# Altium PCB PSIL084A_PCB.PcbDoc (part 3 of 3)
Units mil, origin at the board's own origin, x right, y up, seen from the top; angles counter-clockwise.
Board outline 8750 x 2700 mil, 4 copper layers (Top Layer, Signal Layer 1, Signal Layer 2, Bottom Layer), stack 61.2 mil thick; 274 components, 214 nets, 1279 pads, 354 vias.
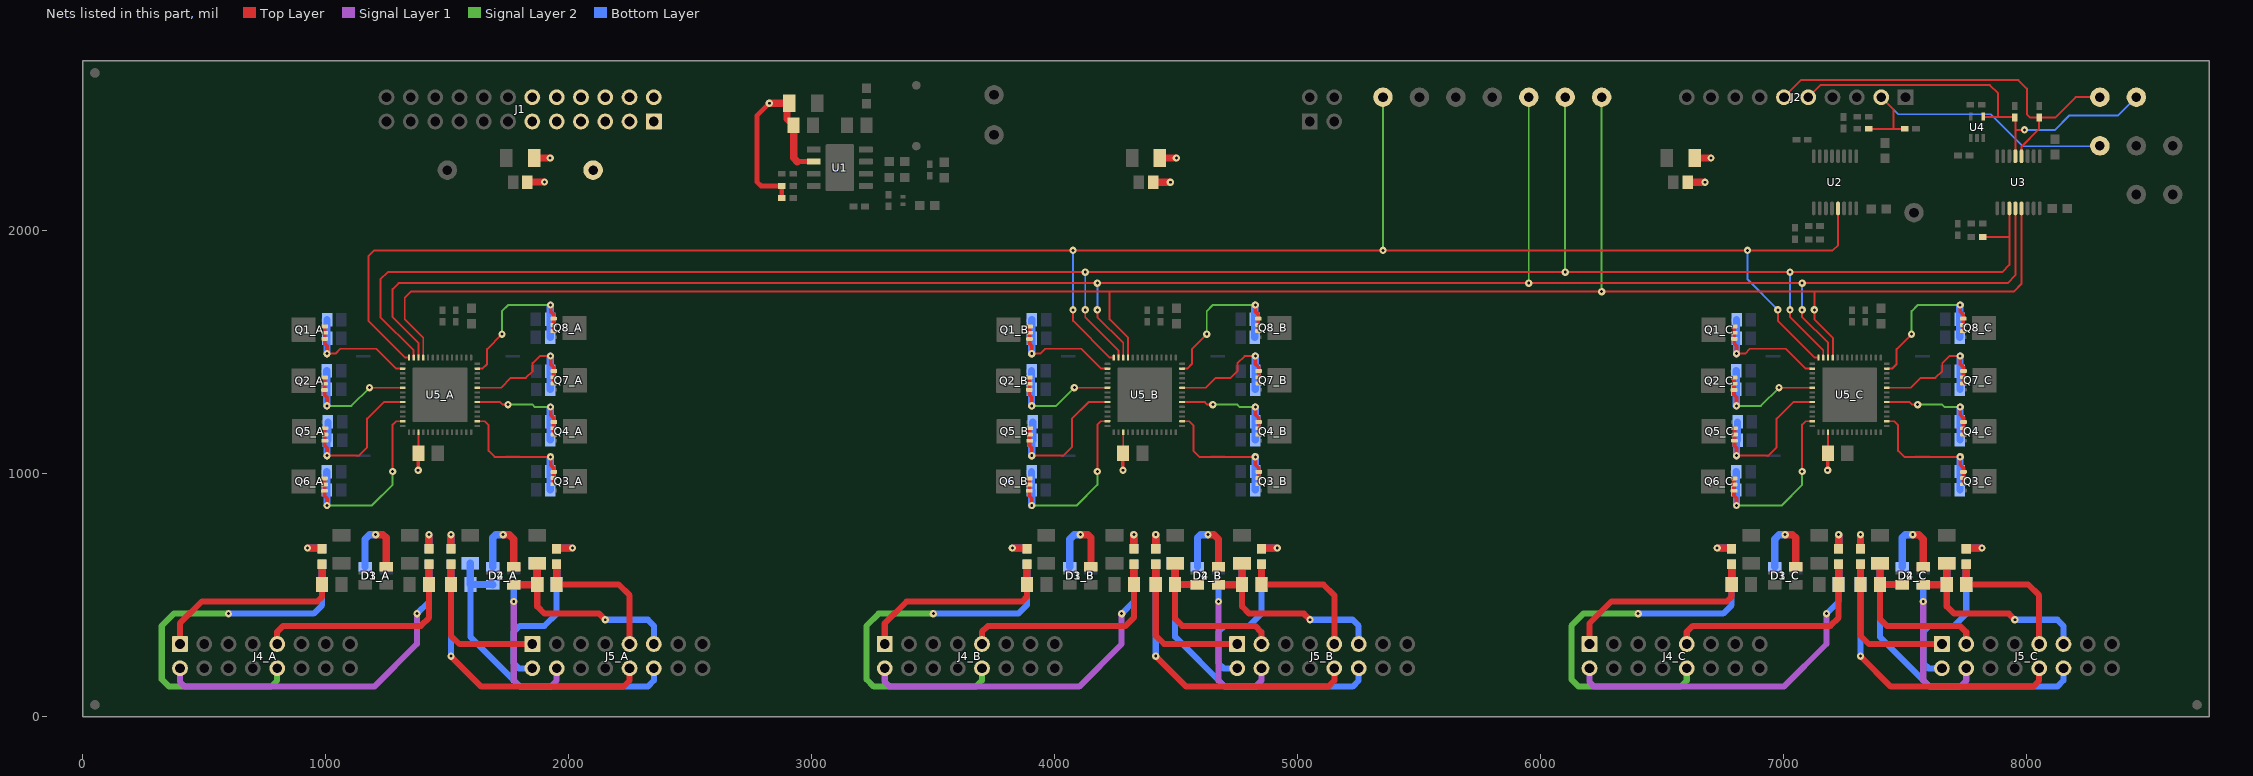
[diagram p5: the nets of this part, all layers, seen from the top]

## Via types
v1: diameter 30, hole 12, Top Layer to Bottom Layer, 282 vias
v2: diameter 19.68, hole 7.87, Top Layer to Bottom Layer, 67 vias
v3: diameter 19.68, hole 7.87, Top Layer to Bottom Layer, tented both sides, 4 vias
v4: diameter 34, hole 16, Top Layer to Bottom Layer, 1 vias

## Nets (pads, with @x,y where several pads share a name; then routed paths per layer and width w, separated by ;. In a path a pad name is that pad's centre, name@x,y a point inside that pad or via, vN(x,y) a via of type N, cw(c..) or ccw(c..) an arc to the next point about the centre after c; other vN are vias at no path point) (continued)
PSE_N5_B: C22_B.2 D2_B.2 F3_B.1 J5_B.3 | length 748.5
  Top Layer w25: C22_B.2@4495,545 4495,403.31 4523.31,375 4824.13,375 4850,349.13 J5_B.3@4850,300
  Top Layer w30: F3_B.1@4495,632.91 C22_B.2@4495,545 4585.2,545 D2_B.2@4586.69,543.5
PSE_N5_C: C22_C.2 D2_C.2 F3_C.1 J5_C.3 | length 748.5
  Top Layer w25: C22_C.2@7395,545 7395,403.31 7423.31,375 7724.13,375 7750,349.13 J5_C.3@7750,300
  Top Layer w30: F3_C.1@7395,632.91 C22_C.2@7395,545 7485.2,545 D2_C.2@7486.69,543.5
PSE_N6_A: C23_A.2 D2_A.3 F4_A.1 J5_A.11 | length 863.4
  Top Layer w25: C23_A.2@1870,545 1870,455 1900,425 2125,425 v1(2150,400)
  Top Layer w30: D2_A.3@1773.31,543.5 1868.5,543.5 C23_A.2@1870,545 F4_A.1@1870,632.91
  Bottom Layer w25: v1(2150,400) 2325,400 2350,375 J5_A.11@2350,300
PSE_N6_B: C23_B.2 D2_B.3 F4_B.1 J5_B.11 | length 863.4
  Top Layer w25: C23_B.2@4770,545 4770,455 4800,425 5025,425 v1(5050,400)
  Top Layer w30: D2_B.3@4673.31,543.5 4768.5,543.5 C23_B.2@4770,545 F4_B.1@4770,632.91
  Bottom Layer w25: v1(5050,400) 5225,400 5250,375 J5_B.11@5250,300
PSE_N6_C: C23_C.2 D2_C.3 F4_C.1 J5_C.11 | length 863.4
  Top Layer w25: C23_C.2@7670,545 7670,455 7700,425 7925,425 v1(7950,400)
  Top Layer w30: D2_C.3@7573.31,543.5 7668.5,543.5 C23_C.2@7670,545 F4_C.1@7670,632.91
  Bottom Layer w25: v1(7950,400) 8125,400 8150,375 J5_C.11@8150,300
PSE_N7_A: C26_A.2 D4_A.2 F7_A.1 J5_A.4 | length 826.1
  Signal Layer 1 w25: v1(1773.31,474.98) 1773.31,150 1798.31,125 1925,125 1950,150 J5_A.4@1950,200
  Bottom Layer w25: v1(1773.31,474.98) D4_A.2@1773.31,543.5
  Bottom Layer w30: D4_A.2@1773.31,543.5 1774.8,545 C26_A.2@1870,545 F7_A.1@1870,632.91
PSE_N7_B: C26_B.2 D4_B.2 F7_B.1 J5_B.4 | length 826.1
  Signal Layer 1 w25: v1(4673.31,474.98) 4673.31,150 4698.31,125 4825,125 4850,150 J5_B.4@4850,200
  Bottom Layer w25: v1(4673.31,474.98) D4_B.2@4673.31,543.5
  Bottom Layer w30: D4_B.2@4673.31,543.5 4674.8,545 C26_B.2@4770,545 F7_B.1@4770,632.91
PSE_N7_C: C26_C.2 D4_C.2 F7_C.1 J5_C.4 | length 826.1
  Signal Layer 1 w25: v1(7573.31,474.98) 7573.31,150 7598.31,125 7725,125 7750,150 J5_C.4@7750,200
  Bottom Layer w25: v1(7573.31,474.98) D4_C.2@7573.31,543.5
  Bottom Layer w30: D4_C.2@7573.31,543.5 7574.8,545 C26_C.2@7670,545 F7_C.1@7670,632.91
PSE_N8_A: C27_A.2 D4_A.3 F8_A.1 J5_A.12 | length 1295.5
  Bottom Layer w25: C27_A.2@1595,545 1595,330 1800,125 2325,125 2350,150 J5_A.12@2350,200
  Bottom Layer w30: F8_A.1@1595,632.91 C27_A.2@1595,545 1685.2,545 D4_A.3@1686.69,543.5
PSE_N8_B: C27_B.2 D4_B.3 F8_B.1 J5_B.12 | length 1295.5
  Bottom Layer w25: C27_B.2@4495,545 4495,330 4700,125 5225,125 5250,150 J5_B.12@5250,200
  Bottom Layer w30: F8_B.1@4495,632.91 C27_B.2@4495,545 4585.2,545 D4_B.3@4586.69,543.5
PSE_N8_C: C27_C.2 D4_C.3 F8_C.1 J5_C.12 | length 1295.5
  Bottom Layer w25: C27_C.2@7395,545 7395,330 7600,125 8125,125 8150,150 J5_C.12@8150,200
  Bottom Layer w30: F8_C.1@7395,632.91 C27_C.2@7395,545 7485.2,545 D4_C.3@7486.69,543.5
PSE_OSS: TP12.1 U2.13 U5_A.56 U5_B.56 U5_C.56 | length 8434
  Top Layer w8: U5_A.56@1342.05,1478.54 1326.46,1478.54 1175,1630 1175,1895 1200,1920 v1(4075,1920) v1(5350,1920) v1(6850,1920) 7200.79,1920 7222.5,1941.71 U2.13@7222.5,2092.72 ; v1(4075,1675) 4075,1630 4226.46,1478.54 U5_B.56@4242.05,1478.54 ; v1(6975,1675) 6975,1630 7126.46,1478.54 U5_C.56@7142.05,1478.54
  Signal Layer 2 w8: v1(5350,1920) TP12.1@5350,2550
  Bottom Layer w8: v1(4075,1675) v1(4075,1920) ; v1(6850,1920) 6850,1800 v1(6975,1675)
PSE_P1_A: C20_A.1 J4_A.1 L2_A.2 | length 849.1
  Top Layer w25: J4_A.1@400,300 400,385 490,475 965,475 985,495 C20_A.1@985,545
  Top Layer w30: C20_A.1@985,545 L2_A.2@985,628.5
PSE_P1_B: C20_B.1 J4_B.1 L2_B.2 | length 849.1
  Top Layer w25: J4_B.1@3300,300 3300,385 3390,475 3865,475 3885,495 C20_B.1@3885,545
  Top Layer w30: C20_B.1@3885,545 L2_B.2@3885,628.5
PSE_P1_C: C20_C.1 J4_C.1 L2_C.2 | length 849.1
  Top Layer w25: J4_C.1@6200,300 6200,385 6290,475 6765,475 6785,495 C20_C.1@6785,545
  Top Layer w30: C20_C.1@6785,545 L2_C.2@6785,628.5
PSE_P2_A: C21_A.1 J4_A.9 L3_A.2 | length 919.1
  Top Layer w25: J4_A.9@800,300 800,350 825,375 1391.3,375 1425,408.7 C21_A.1@1425,545
  Top Layer w30: C21_A.1@1425,545 L3_A.2@1425,628.5
PSE_P2_B: C21_B.1 J4_B.9 L3_B.2 | length 919.1
  Top Layer w25: J4_B.9@3700,300 3700,350 3725,375 4291.3,375 4325,408.7 C21_B.1@4325,545
  Top Layer w30: C21_B.1@4325,545 L3_B.2@4325,628.5
PSE_P2_C: C21_C.1 J4_C.9 L3_C.2 | length 919.1
  Top Layer w25: J4_C.9@6600,300 6600,350 6625,375 7191.3,375 7225,408.7 C21_C.1@7225,545
  Top Layer w30: C21_C.1@7225,545 L3_C.2@7225,628.5
PSE_P3_A: C24_A.1 J4_A.2 L6_A.2 | length 1460
  Signal Layer 1 w25: J4_A.2@400,200 400,145 420,125 1200,125 1375.02,300.02 v1(1375.02,425)
  Bottom Layer w25: v1(1375.02,425) 1425,474.98 C24_A.1@1425,545
  Bottom Layer w30: C24_A.1@1425,545 L6_A.2@1425,628.5
PSE_P3_B: C24_B.1 J4_B.2 L6_B.2 | length 1460
  Signal Layer 1 w25: J4_B.2@3300,200 3300,145 3320,125 4100,125 4275.02,300.02 v1(4275.02,425)
  Bottom Layer w25: v1(4275.02,425) 4325,474.98 C24_B.1@4325,545
  Bottom Layer w30: C24_B.1@4325,545 L6_B.2@4325,628.5
PSE_P3_C: C24_C.1 J4_C.2 L6_C.2 | length 1460
  Signal Layer 1 w25: J4_C.2@6200,200 6200,145 6220,125 7000,125 7175.02,300.02 v1(7175.02,425)
  Bottom Layer w25: v1(7175.02,425) 7225,474.98 C24_C.1@7225,545
  Bottom Layer w30: C24_C.1@7225,545 L6_C.2@7225,628.5
PSE_P4_A: C25_A.1 J4_A.10 L7_A.2 | length 1631.5
  Signal Layer 2 w25: v1(600,425) 375,425 325,375 325,155 355,125 775,125 800,150 J4_A.10@800,200
  Bottom Layer w25: v1(600,425) 950,425 985,460 C25_A.1@985,545
  Bottom Layer w30: C25_A.1@985,545 L7_A.2@985,628.5
PSE_P4_B: C25_B.1 J4_B.10 L7_B.2 | length 1631.5
  Signal Layer 2 w25: v1(3500,425) 3275,425 3225,375 3225,155 3255,125 3675,125 3700,150 J4_B.10@3700,200
  Bottom Layer w25: v1(3500,425) 3850,425 3885,460 C25_B.1@3885,545
  Bottom Layer w30: C25_B.1@3885,545 L7_B.2@3885,628.5
PSE_P4_C: C25_C.1 J4_C.10 L7_C.2 | length 1631.5
  Signal Layer 2 w25: v1(6400,425) 6175,425 6125,375 6125,155 6155,125 6575,125 6600,150 J4_C.10@6600,200
  Bottom Layer w25: v1(6400,425) 6750,425 6785,460 C25_C.1@6785,545
  Bottom Layer w30: C25_C.1@6785,545 L7_C.2@6785,628.5
PSE_P5_A: C22_A.1 J5_A.1 L4_A.2 | length 643.2
  Top Layer w25: C22_A.1@1515,545 1515,334.74 1549.74,300 J5_A.1@1850,300
  Top Layer w30: C22_A.1@1515,545 L4_A.2@1515,628.5
PSE_P5_B: C22_B.1 J5_B.1 L4_B.2 | length 643.2
  Top Layer w25: C22_B.1@4415,545 4415,334.74 4449.74,300 J5_B.1@4750,300
  Top Layer w30: C22_B.1@4415,545 L4_B.2@4415,628.5
PSE_P5_C: C22_C.1 J5_C.1 L4_C.2 | length 643.2
  Top Layer w25: C22_C.1@7315,545 7315,334.74 7349.74,300 J5_C.1@7650,300
  Top Layer w30: C22_C.1@7315,545 L4_C.2@7315,628.5
PSE_P6_A: C23_A.1 J5_A.9 L5_A.2 | length 602.1
  Top Layer w25: C23_A.1@1950,545 2205,545 2250,500 J5_A.9@2250,300
  Top Layer w30: C23_A.1@1950,545 L5_A.2@1950,628.5
PSE_P6_B: C23_B.1 J5_B.9 L5_B.2 | length 602.1
  Top Layer w25: C23_B.1@4850,545 5105,545 5150,500 J5_B.9@5150,300
  Top Layer w30: C23_B.1@4850,545 L5_B.2@4850,628.5
PSE_P6_C: C23_C.1 J5_C.9 L5_C.2 | length 602.1
  Top Layer w25: C23_C.1@7750,545 8005,545 8050,500 J5_C.9@8050,300
  Top Layer w30: C23_C.1@7750,545 L5_C.2@7750,628.5
PSE_P7_A: C26_A.1 J5_A.2 L8_A.2 | length 625.2
  Bottom Layer w25: J5_A.2@1850,200 1795,200 1773.31,221.69 1773.31,350 1798.31,375 1900,375 1950,425 C26_A.1@1950,545
  Bottom Layer w30: C26_A.1@1950,545 L8_A.2@1950,628.5
PSE_P7_B: C26_B.1 J5_B.2 L8_B.2 | length 625.2
  Bottom Layer w25: J5_B.2@4750,200 4695,200 4673.31,221.69 4673.31,350 4698.31,375 4800,375 4850,425 C26_B.1@4850,545
  Bottom Layer w30: C26_B.1@4850,545 L8_B.2@4850,628.5
PSE_P7_C: C26_C.1 J5_C.2 L8_C.2 | length 625.2
  Bottom Layer w25: J5_C.2@7650,200 7595,200 7573.31,221.69 7573.31,350 7598.31,375 7700,375 7750,425 C26_C.1@7750,545
  Bottom Layer w30: C26_C.1@7750,545 L8_C.2@7750,628.5
PSE_P8_A: C27_A.1 J5_A.10 L9_A.2 | length 1225.6
  Top Layer w25: v1(1515,250) 1640,125 2225,125 2250,150 J5_A.10@2250,200
  Bottom Layer w25: v1(1515,250) C27_A.1@1515,545
  Bottom Layer w30: C27_A.1@1515,545 L9_A.2@1515,628.5
PSE_P8_B: C27_B.1 J5_B.10 L9_B.2 | length 1225.6
  Top Layer w25: v1(4415,250) 4540,125 5125,125 5150,150 J5_B.10@5150,200
  Bottom Layer w25: v1(4415,250) C27_B.1@4415,545
  Bottom Layer w30: C27_B.1@4415,545 L9_B.2@4415,628.5
PSE_P8_C: C27_C.1 J5_C.10 L9_C.2 | length 1225.6
  Top Layer w25: v1(7315,250) 7440,125 8025,125 8050,150 J5_C.10@8050,200
  Bottom Layer w25: v1(7315,250) C27_C.1@7315,545
  Bottom Layer w30: C27_C.1@7315,545 L9_C.2@7315,628.5
PSE_S1_A: Q1_A.1 Q1_A.2 Q1_A.3 R21_A.1 R22_A.1 U5_A.2 | length 608.1
  Top Layer w8: v1(1005,1495) 1040,1495 1060,1515 1208.27,1515 1290,1433.27 U5_A.2@1316.46,1433.27
  Top Layer w15: Q1_A.3@995.69,1606.71 Q1_A.2@995.69,1581.12 Q1_A.1@995.69,1555.53 995.69,1536.73 1005,1527.42 v1(1005,1495)
  Bottom Layer w30: v1(1005,1495) 1005.14,1495.14 R22_A.1@1005.14,1558.92 R21_A.1@1005.14,1633.92
PSE_S1_B: Q1_B.1 Q1_B.2 Q1_B.3 R21_B.1 R22_B.1 U5_B.2 | length 608.1
  Top Layer w8: v1(3905,1495) 3940,1495 3960,1515 4108.27,1515 4190,1433.27 U5_B.2@4216.46,1433.27
  Top Layer w15: Q1_B.3@3895.69,1606.71 Q1_B.2@3895.69,1581.12 Q1_B.1@3895.69,1555.53 3895.69,1536.73 3905,1527.42 v1(3905,1495)
  Bottom Layer w30: v1(3905,1495) 3905.14,1495.14 R22_B.1@3905.14,1558.92 R21_B.1@3905.14,1633.92
PSE_S1_C: Q1_C.1 Q1_C.2 Q1_C.3 R21_C.1 R22_C.1 U5_C.2 | length 608.1
  Top Layer w8: v1(6805,1495) 6840,1495 6860,1515 7008.27,1515 7090,1433.27 U5_C.2@7116.46,1433.27
  Top Layer w15: Q1_C.3@6795.69,1606.71 Q1_C.2@6795.69,1581.12 Q1_C.1@6795.69,1555.53 6795.69,1536.73 6805,1527.42 v1(6805,1495)
  Bottom Layer w30: v1(6805,1495) 6805.14,1495.14 R22_C.1@6805.14,1558.92 R21_C.1@6805.14,1633.92
PSE_S2_A: Q2_A.1 Q2_A.2 Q2_A.3 R23_A.1 R24_A.1 U5_A.6 | length 608.1
  Top Layer w8: v1(1180,1355) 1180.47,1354.53 U5_A.6@1316.46,1354.53
  Top Layer w15: Q2_A.3@994.59,1396.71 Q2_A.2@994.59,1371.12 Q2_A.1@994.59,1345.53 994.59,1325.55 1005,1315.14 v1(1005,1280)
  Signal Layer 2 w8: v1(1005,1280) 1105,1280 v1(1180,1355)
  Bottom Layer w30: R23_A.1@1004.04,1423.92 R24_A.1@1004.04,1348.92 1004.04,1280.96 v1(1005,1280)
PSE_S2_B: Q2_B.1 Q2_B.2 Q2_B.3 R23_B.1 R24_B.1 U5_B.6 | length 608.1
  Top Layer w8: v1(4080,1355) 4080.47,1354.53 U5_B.6@4216.46,1354.53
  Top Layer w15: Q2_B.3@3894.59,1396.71 Q2_B.2@3894.59,1371.12 Q2_B.1@3894.59,1345.53 3894.59,1325.55 3905,1315.14 v1(3905,1280)
  Signal Layer 2 w8: v1(3905,1280) 4005,1280 v1(4080,1355)
  Bottom Layer w30: R23_B.1@3904.04,1423.92 R24_B.1@3904.04,1348.92 3904.04,1280.96 v1(3905,1280)
PSE_S2_C: Q2_C.1 Q2_C.2 Q2_C.3 R23_C.1 R24_C.1 U5_C.6 | length 608.1
  Top Layer w8: v1(6980,1355) 6980.47,1354.53 U5_C.6@7116.46,1354.53
  Top Layer w15: Q2_C.3@6794.59,1396.71 Q2_C.2@6794.59,1371.12 Q2_C.1@6794.59,1345.53 6794.59,1325.55 6805,1315.14 v1(6805,1280)
  Signal Layer 2 w8: v1(6805,1280) 6905,1280 v1(6980,1355)
  Bottom Layer w30: R23_C.1@6804.04,1423.92 R24_C.1@6804.04,1348.92 6804.04,1280.96 v1(6805,1280)
PSE_S3_A: Q5_A.1 Q5_A.2 Q5_A.3 R29_A.1 R30_A.1 U5_A.9 | length 728.3
  Top Layer w8: v1(1005,1075) 1135,1075 1170,1110 1170,1227.07 1238.4,1295.47 U5_A.9@1316.46,1295.47
  Top Layer w15: Q5_A.3@996.42,1187.8 Q5_A.2@996.42,1162.2 Q5_A.1@996.42,1136.61 996.42,1116 1005,1107.42 v1(1005,1075)
  Bottom Layer w30: v1(1005,1075) 1005,1134.88 R30_A.1@1009.04,1138.92 R29_A.1@1009.04,1213.92
PSE_S3_B: Q5_B.1 Q5_B.2 Q5_B.3 R29_B.1 R30_B.1 U5_B.9 | length 728.3
  Top Layer w8: v1(3905,1075) 4035,1075 4070,1110 4070,1227.07 4138.4,1295.47 U5_B.9@4216.46,1295.47
  Top Layer w15: Q5_B.3@3896.42,1187.8 Q5_B.2@3896.42,1162.2 Q5_B.1@3896.42,1136.61 3896.42,1116 3905,1107.42 v1(3905,1075)
  Bottom Layer w30: v1(3905,1075) 3905,1134.88 R30_B.1@3909.04,1138.92 R29_B.1@3909.04,1213.92
PSE_S3_C: Q5_C.1 Q5_C.2 Q5_C.3 R29_C.1 R30_C.1 U5_C.9 | length 728.3
  Top Layer w8: v1(6805,1075) 6935,1075 6970,1110 6970,1227.07 7038.4,1295.47 U5_C.9@7116.46,1295.47
  Top Layer w15: Q5_C.3@6796.42,1187.8 Q5_C.2@6796.42,1162.2 Q5_C.1@6796.42,1136.61 6796.42,1116 6805,1107.42 v1(6805,1075)
  Bottom Layer w30: v1(6805,1075) 6805,1134.88 R30_C.1@6809.04,1138.92 R29_C.1@6809.04,1213.92
PSE_S4_A: Q6_A.1 Q6_A.2 Q6_A.3 R31_A.1 R32_A.1 U5_A.13 | length 855.5
  Top Layer w8: v1(1275,1010) 1275,1202.66 1289.07,1216.73 U5_A.13@1316.46,1216.73
  Top Layer w15: Q6_A.3@994.59,981.71 Q6_A.2@994.59,956.12 Q6_A.1@994.59,930.53 994.59,910.41 1005,900 v1(1005,870)
  Signal Layer 2 w8: v1(1005,870) 1190,870 1275,955 v1(1275,1010)
  Bottom Layer w30: R31_A.1@1004.04,1008.92 R32_A.1@1004.04,933.92 1005,932.95 v1(1005,870)
PSE_S4_B: Q6_B.1 Q6_B.2 Q6_B.3 R31_B.1 R32_B.1 U5_B.13 | length 855.5
  Top Layer w8: v1(4175,1010) 4175,1202.66 4189.07,1216.73 U5_B.13@4216.46,1216.73
  Top Layer w15: Q6_B.3@3894.59,981.71 Q6_B.2@3894.59,956.12 Q6_B.1@3894.59,930.53 3894.59,910.41 3905,900 v1(3905,870)
  Signal Layer 2 w8: v1(3905,870) 4090,870 4175,955 v1(4175,1010)
  Bottom Layer w30: R31_B.1@3904.04,1008.92 R32_B.1@3904.04,933.92 3905,932.95 v1(3905,870)
PSE_S4_C: Q6_C.1 Q6_C.2 Q6_C.3 R31_C.1 R32_C.1 U5_C.13 | length 855.5
  Top Layer w8: v1(7075,1010) 7075,1202.66 7089.07,1216.73 U5_C.13@7116.46,1216.73
  Top Layer w15: Q6_C.3@6794.59,981.71 Q6_C.2@6794.59,956.12 Q6_C.1@6794.59,930.53 6794.59,910.41 6805,900 v1(6805,870)
  Signal Layer 2 w8: v1(6805,870) 6990,870 7075,955 v1(7075,1010)
  Bottom Layer w30: R31_C.1@6804.04,1008.92 R32_C.1@6804.04,933.92 6805,932.95 v1(6805,870)
PSE_S5_A: Q3_A.1 Q3_A.2 Q3_A.3 R25_A.1 R26_A.1 U5_A.30 | length 677.5
  Top Layer w8: U5_A.30@1623.54,1216.73 1653.27,1216.73 1670,1200 1670,1095 1695,1070 v1(1925,1070)
  Top Layer w15: v1(1925,1070) 1925,1037.46 1938.58,1023.88 Q3_A.1@1938.58,1008.39 Q3_A.2@1938.58,982.8 Q3_A.3@1938.58,957.2
  Bottom Layer w30: R26_A.1@1924.13,935 R25_A.1@1924.13,1010 1924.13,1069.13 v1(1925,1070)
PSE_S5_B: Q3_B.1 Q3_B.2 Q3_B.3 R25_B.1 R26_B.1 U5_B.30 | length 677.5
  Top Layer w8: U5_B.30@4523.54,1216.73 4553.27,1216.73 4570,1200 4570,1095 4595,1070 v1(4825,1070)
  Top Layer w15: v1(4825,1070) 4825,1037.46 4838.58,1023.88 Q3_B.1@4838.58,1008.39 Q3_B.2@4838.58,982.8 Q3_B.3@4838.58,957.2
  Bottom Layer w30: R26_B.1@4824.13,935 R25_B.1@4824.13,1010 4824.13,1069.13 v1(4825,1070)
PSE_S5_C: Q3_C.1 Q3_C.2 Q3_C.3 R25_C.1 R26_C.1 U5_C.30 | length 677.5
  Top Layer w8: U5_C.30@7423.54,1216.73 7453.27,1216.73 7470,1200 7470,1095 7495,1070 v1(7725,1070)
  Top Layer w15: v1(7725,1070) 7725,1037.46 7738.58,1023.88 Q3_C.1@7738.58,1008.39 Q3_C.2@7738.58,982.8 Q3_C.3@7738.58,957.2
  Bottom Layer w30: R26_C.1@7724.13,935 R25_C.1@7724.13,1010 7724.13,1069.13 v1(7725,1070)
PSE_S6_A: Q4_A.1 Q4_A.2 Q4_A.3 R27_A.1 R28_A.1 U5_A.34 | length 563.7
  Top Layer w8: U5_A.34@1623.54,1295.47 1716.91,1295.47 1727.39,1285 v1(1750,1285)
  Top Layer w15: v1(1925,1275) 1925,1243.54 1938.58,1229.96 Q4_A.1@1938.58,1213.39 Q4_A.2@1938.58,1187.8 Q4_A.3@1938.58,1162.2
  Signal Layer 2 w8: v1(1750,1285) 1850.79,1285 1860.79,1275 v1(1925,1275)
  Bottom Layer w30: R28_A.1@1924.13,1140 R27_A.1@1924.13,1215 1924.13,1274.13 v1(1925,1275)
PSE_S6_B: Q4_B.1 Q4_B.2 Q4_B.3 R27_B.1 R28_B.1 U5_B.34 | length 563.7
  Top Layer w8: U5_B.34@4523.54,1295.47 4616.91,1295.47 4627.39,1285 v1(4650,1285)
  Top Layer w15: v1(4825,1275) 4825,1243.54 4838.58,1229.96 Q4_B.1@4838.58,1213.39 Q4_B.2@4838.58,1187.8 Q4_B.3@4838.58,1162.2
  Signal Layer 2 w8: v1(4650,1285) 4750.79,1285 4760.79,1275 v1(4825,1275)
  Bottom Layer w30: R28_B.1@4824.13,1140 R27_B.1@4824.13,1215 4824.13,1274.13 v1(4825,1275)
PSE_S6_C: Q4_C.1 Q4_C.2 Q4_C.3 R27_C.1 R28_C.1 U5_C.34 | length 563.7
  Top Layer w8: U5_C.34@7423.54,1295.47 7516.91,1295.47 7527.39,1285 v1(7550,1285)
  Top Layer w15: v1(7725,1275) 7725,1243.54 7738.58,1229.96 Q4_C.1@7738.58,1213.39 Q4_C.2@7738.58,1187.8 Q4_C.3@7738.58,1162.2
  Signal Layer 2 w8: v1(7550,1285) 7650.79,1285 7660.79,1275 v1(7725,1275)
  Bottom Layer w30: R28_C.1@7724.13,1140 R27_C.1@7724.13,1215 7724.13,1274.13 v1(7725,1275)
PSE_S7_A: Q7_A.1 Q7_A.2 Q7_A.3 R33_A.1 R34_A.1 U5_A.37 | length 631
  Top Layer w8: U5_A.37@1623.54,1354.53 1721.5,1354.53 1761.97,1395 1823.5,1395 1851.3,1422.8 1851.3,1455.43 1880.87,1485 v1(1925,1485)
  Top Layer w15: v1(1925,1485) 1925,1452.39 1938.58,1438.81 Q7_A.1@1938.58,1423.39 Q7_A.2@1938.58,1397.8 Q7_A.3@1938.58,1372.2
  Bottom Layer w30: R34_A.1@1924.13,1347.39 R33_A.1@1924.13,1422.39 1924.13,1484.13 v1(1925,1485)
PSE_S7_B: Q7_B.1 Q7_B.2 Q7_B.3 R33_B.1 R34_B.1 U5_B.37 | length 631
  Top Layer w8: U5_B.37@4523.54,1354.53 4621.5,1354.53 4661.97,1395 4723.5,1395 4751.3,1422.8 4751.3,1455.43 4780.87,1485 v1(4825,1485)
  Top Layer w15: v1(4825,1485) 4825,1452.39 4838.58,1438.81 Q7_B.1@4838.58,1423.39 Q7_B.2@4838.58,1397.8 Q7_B.3@4838.58,1372.2
  Bottom Layer w30: R34_B.1@4824.13,1347.39 R33_B.1@4824.13,1422.39 4824.13,1484.13 v1(4825,1485)
PSE_S7_C: Q7_C.1 Q7_C.2 Q7_C.3 R33_C.1 R34_C.1 U5_C.37 | length 631
  Top Layer w8: U5_C.37@7423.54,1354.53 7521.5,1354.53 7561.97,1395 7623.5,1395 7651.3,1422.8 7651.3,1455.43 7680.87,1485 v1(7725,1485)
  Top Layer w15: v1(7725,1485) 7725,1452.39 7738.58,1438.81 Q7_C.1@7738.58,1423.39 Q7_C.2@7738.58,1397.8 Q7_C.3@7738.58,1372.2
  Bottom Layer w30: R34_C.1@7724.13,1347.39 R33_C.1@7724.13,1422.39 7724.13,1484.13 v1(7725,1485)
PSE_S8_A: Q8_A.1 Q8_A.2 Q8_A.3 R35_A.1 R36_A.1 U5_A.41 | length 748.3
  Top Layer w8: U5_A.41@1623.54,1433.27 1644.62,1433.27 1663.58,1452.23 1663.58,1513.58 v1(1725,1575)
  Top Layer w15: v1(1925,1695) 1925,1667.99 1937.48,1655.51 Q8_A.1@1937.48,1638.87 Q8_A.2@1937.48,1613.28 Q8_A.3@1937.48,1587.69
  Signal Layer 2 w8: v1(1725,1575) 1725,1670 1750,1695 v1(1925,1695)
  Bottom Layer w30: R36_A.1@1923.03,1561.5 R35_A.1@1923.03,1636.5 1923.03,1693.03 v1(1925,1695)
PSE_S8_B: Q8_B.1 Q8_B.2 Q8_B.3 R35_B.1 R36_B.1 U5_B.41 | length 748.3
  Top Layer w8: U5_B.41@4523.54,1433.27 4544.62,1433.27 4563.58,1452.23 4563.58,1513.58 v1(4625,1575)
  Top Layer w15: v1(4825,1695) 4825,1667.99 4837.48,1655.51 Q8_B.1@4837.48,1638.87 Q8_B.2@4837.48,1613.28 Q8_B.3@4837.48,1587.69
  Signal Layer 2 w8: v1(4625,1575) 4625,1670 4650,1695 v1(4825,1695)
  Bottom Layer w30: R36_B.1@4823.03,1561.5 R35_B.1@4823.03,1636.5 4823.03,1693.03 v1(4825,1695)
PSE_S8_C: Q8_C.1 Q8_C.2 Q8_C.3 R35_C.1 R36_C.1 U5_C.41 | length 748.3
  Top Layer w8: U5_C.41@7423.54,1433.27 7444.62,1433.27 7463.58,1452.23 7463.58,1513.58 v1(7525,1575)
  Top Layer w15: v1(7725,1695) 7725,1667.99 7737.48,1655.51 Q8_C.1@7737.48,1638.87 Q8_C.2@7737.48,1613.28 Q8_C.3@7737.48,1587.69
  Signal Layer 2 w8: v1(7525,1575) 7525,1670 7550,1695 v1(7725,1695)
  Bottom Layer w30: R36_C.1@7723.03,1561.5 R35_C.1@7723.03,1636.5 7723.03,1693.03 v1(7725,1695)
PSE_SCL_A: TP16.1 U3.13 U5_A.53 U5_B.53 U5_C.53 | length 8670.5
  Top Layer w8: U5_A.53@1401.1,1478.54 1401.1,1559.38 1325,1635.48 1325,1725 1350,1750 4225,1750 ; U5_B.53@4301.1,1478.54 4301.1,1559.38 4225,1635.48 4225,1750 ; U5_C.53@7201.1,1478.54 7201.1,1559.38 7125,1635.48 v1(7125,1675) 7125,1750 ; U3.13@7977.5,2092.72 7977.5,1782.5 7945,1750 7125,1750 ; 4225,1750 v1(6250,1750) 7125,1750
  Signal Layer 2 w8: v1(6250,1750) TP16.1@6250,2550
PSE_SDAI_A: TP17.1 U3.12 U5_A.54 U5_B.54 U5_C.54 | length 8768.1
  Top Layer w8: U5_A.54@1381.42,1478.54 1381.42,1538.96 1275,1645.37 1275,1760 1300,1785 v1(4175,1785) v1(5950,1785) v1(7075,1785) 7920,1785 7952.5,1817.5 U3.12@7952.5,2092.72 ; v1(4175,1675) 4175,1645.37 4281.42,1538.96 U5_B.54@4281.42,1478.54 ; v1(7075,1675) 7075,1645.37 7181.42,1538.96 U5_C.54@7181.42,1478.54
  Signal Layer 2 w8: v1(5950,1785) TP17.1@5950,2550
  Bottom Layer w8: v1(4175,1675) v1(4175,1785) ; v1(7075,1675) v1(7075,1785)
PSE_SDAO_A: R16.1 TP18.1 U3.11 U5_A.55 U5_B.55 U5_C.55 | length 8983.2
  Top Layer w8: U5_A.55@1361.73,1478.54 1361.73,1508.29 1225,1645.02 1225,1800 1255,1830 v1(4125,1830) v1(6100,1830) v1(7025,1830) 7897.39,1830 7927.5,1860.11 7927.5,1975.11 ; v1(4125,1675) 4125,1645.02 4261.73,1508.29 U5_B.55@4261.73,1478.54 ; v1(7025,1675) 7025,1645.02 7161.73,1508.29 U5_C.55@7161.73,1478.54 ; R16.1@7818.62,1975 7927.39,1975 7927.5,1975.11 ; U3.11@7927.5,2092.72 7927.5,1975.11
  Signal Layer 2 w8: v1(6100,1830) TP18.1@6100,2550
  Bottom Layer w8: v1(4125,1675) v1(4125,1830) ; v1(7025,1675) v1(7025,1830)
RESET: J2.2 R8.2 R10.1 TP6.1 | length 1283.3
  Top Layer w8: R10.1@7348.62,2420 7451.02,2420 ; J2.2@7400,2550 7451.02,2498.98 7451.02,2420 ; R8.2@7496.38,2420 7451.02,2420
  Bottom Layer w8: J2.2@7400,2550 7470,2480 7850.71,2480 7982.58,2348.13 8298.13,2348.13 TP6.1@8300,2350
SCL: J2.6 R18.2 TP10.1 U3.4 | length 1677.9
  Top Layer w8: J2.6@7000,2550 7070,2620 7965,2620 8000,2585 8000,2480 8013.62,2466.38 R18.2@8050,2466.38 ; U3.4@7977.5,2307.28 7977.5,2346.95 8050,2419.45 R18.2@8050,2466.38 ; TP10.1@8300,2550 8200,2550 8116.38,2466.38 R18.2@8050,2466.38
SDA: J2.5 R17.2 TP9.1 U3.5 U4.4 | length 1758.1
  Top Layer w8: J2.5@7100,2550 7150,2600 7847.5,2600 7880,2567.5 7880,2468.62 ; U4.4@7820,2470 7821.38,2468.62 7880,2468.62 ; U3.5@7952.5,2307.28 7952.5,2415 ; v1(7990,2415.71) 7953.21,2415.71 7952.5,2415 ; 7880,2468.62 7947.76,2468.62 R17.2@7950,2466.38 7952.5,2463.88 7952.5,2415
  Bottom Layer w8: v1(7990,2415.71) 8115.71,2415.71 8175,2475 8375,2475 TP9.1@8450,2550
VPWR: C4.2 C6.2 C15.2 C17_A.1 C17_B.1 C17_C.1 C18.2 C19.2 C28.2 C29.2 C30.2 D1_A.4 D1_B.4 D1_C.4 D2_A.4 D2_B.4 D2_C.4 D3_A.4 D3_B.4 D3_C.4 D4_A.4 D4_B.4 D4_C.4 J1.1 J1.2 J1.3 J1.4 J1.5 J1.6 J1.7 J1.8 J1.9 J1.10 J1.11 J1.12 L2_A.1 L2_B.1 L2_C.1 L3_A.1 L3_B.1 L3_C.1 L4_A.1 L4_B.1 L4_C.1 L5_A.1 L5_B.1 L5_C.1 L6_A.1 L6_B.1 L6_C.1 L7_A.1 L7_B.1 L7_C.1 L8_A.1 L8_B.1 L8_C.1 L9_A.1 L9_B.1 L9_C.1 R1.1 R2.1 TP2.1 U1.2 U5_A.17 U5_B.17 U5_C.17 | length 5257.2
  Top Layer w8: C17_A.1@1380.79,1085 1381.42,1085.63 U5_A.17@1381.42,1171.46 ; C17_B.1@4280.79,1085 4281.42,1085.63 U5_B.17@4281.42,1171.46 ; C17_C.1@7180.79,1085 7181.42,1085.63 U5_C.17@7181.42,1171.46
  Top Layer w15: v1(1380,1015) 1380,1084.21 C17_A.1@1380.79,1085 ; v1(4280,1015) 4280,1084.21 C17_B.1@4280.79,1085 ; v1(7180,1015) 7180,1084.21 C17_C.1@7180.79,1085
  Top Layer w20: v1(2825,2525) 2775,2475 2775,2200.79 2790.79,2185 R2.1@2876.38,2185 R1.1@2876.38,2135 ; 2939.99,2285 U1.2@3007.72,2285
  Top Layer w30: v1(925,695) 981.5,695 L2_A.1@985,691.5 ; v1(1205,750) 1235,750 1248.31,736.69 D1_A.4@1248.31,618.31 ; L3_A.1@1425,691.5 v1(1425,750) ; L4_A.1@1515,691.5 v1(1515,750) ; v1(1730,750) 1755,750 1773.31,731.69 D2_A.4@1773.31,618.31 ; C18.2@1829.53,2200 1830.31,2200.79 v1(1900,2200.79) ; C19.2@1853.15,2300 v1(1923.03,2300) ; L5_A.1@1950,691.5 1953.5,695 v1(2015,695) ; v1(2825,2525) 2898.07,2525 2898.07,2461.93 C4.2@2925,2435 2925,2300 2939.99,2285 ; v1(3825,695) 3881.5,695 L2_B.1@3885,691.5 ; v1(4105,750) 4135,750 4148.31,736.69 D1_B.4@4148.31,618.31 ; L3_B.1@4325,691.5 v1(4325,750) ; C28.2@4404.53,2200 v1(4475,2200) ; L4_B.1@4415,691.5 v1(4415,750) ; C29.2@4428.15,2300 v1(4500,2300) ; v1(4630,750) 4655,750 4673.31,731.69 D2_B.4@4673.31,618.31 ; L5_B.1@4850,691.5 4853.5,695 v1(4915,695) ; C30.2@6604.53,2200 v1(6675,2200) ; C15.2@6628.15,2300 v1(6700,2300) ; v1(6725,695) 6781.5,695 L2_C.1@6785,691.5 ; v1(7005,750) 7035,750 7048.31,736.69 D1_C.4@7048.31,618.31 ; L3_C.1@7225,691.5 v1(7225,750) ; L4_C.1@7315,691.5 v1(7315,750) ; v1(7530,750) 7555,750 7573.31,731.69 D2_C.4@7573.31,618.31 ; L5_C.1@7750,691.5 7753.5,695 v1(7815,695)
  Bottom Layer w30: v1(925,695) 981.5,695 L7_A.1@985,691.5 ; D3_A.4@1161.69,618.31 1161.69,731.69 1180,750 v1(1205,750) ; L6_A.1@1425,691.5 v1(1425,750) ; L9_A.1@1515,691.5 v1(1515,750) ; D4_A.4@1686.69,618.31 1686.69,737.48 1699.21,750 v1(1730,750) ; L8_A.1@1950,691.5 1953.5,695 v1(2015,695) ; v1(3825,695) 3881.5,695 L7_B.1@3885,691.5 ; D3_B.4@4061.69,618.31 4061.69,731.69 4080,750 v1(4105,750) ; L6_B.1@4325,691.5 v1(4325,750) ; L9_B.1@4415,691.5 v1(4415,750) ; D4_B.4@4586.69,618.31 4586.69,737.48 4599.21,750 v1(4630,750) ; L8_B.1@4850,691.5 4853.5,695 v1(4915,695) ; v1(6725,695) 6781.5,695 L7_C.1@6785,691.5 ; D3_C.4@6961.69,618.31 6961.69,731.69 6980,750 v1(7005,750) ; L6_C.1@7225,691.5 v1(7225,750) ; L9_C.1@7315,691.5 v1(7315,750) ; D4_C.4@7486.69,618.31 7486.69,737.48 7499.21,750 v1(7530,750) ; L8_C.1@7750,691.5 7753.5,695 v1(7815,695)
pads on no net: FID1.1 FID2.1 FID3.1 FID4.1 FID5.1 FID6.1 J2.8 J4_A.5 J4_A.6 J4_A.7 J4_A.8 J4_A.13 J4_A.14 J4_A.15 J4_A.16 J4_B.5 J4_B.6 J4_B.7 J4_B.8 J4_B.13 J4_B.14 J4_B.15 J4_B.16 J4_C.5 J4_C.6 J4_C.7 J4_C.8 J4_C.13 J4_C.14 J4_C.15 J4_C.16 J5_A.5 J5_A.6 J5_A.7 J5_A.8 J5_A.13 J5_A.14 J5_A.15 J5_A.16 J5_B.5 J5_B.6 J5_B.7 J5_B.8 J5_B.13 J5_B.14 J5_B.15 J5_B.16 J5_C.5 J5_C.6 J5_C.7 J5_C.8 J5_C.13 J5_C.14 J5_C.15 J5_C.16 LBL1.0 Q1_A.9@888.41,1555.53 Q1_A.9@888.41,1581.12 Q1_A.9@888.41,1606.71 Q1_A.9@888.41,1632.3 Q1_A.9@907.2,1567.84 Q1_A.9@907.2,1620 Q1_A.9@921.77,1593.92 Q1_A.9@942.83,1567.84 Q1_A.9@942.83,1620 Q1_B.9@3788.41,1555.53 Q1_B.9@3788.41,1581.12 Q1_B.9@3788.41,1606.71 Q1_B.9@3788.41,1632.3 Q1_B.9@3807.2,1567.84 Q1_B.9@3807.2,1620 Q1_B.9@3821.77,1593.92 Q1_B.9@3842.83,1567.84 Q1_B.9@3842.83,1620 Q1_C.9@6688.41,1555.53 Q1_C.9@6688.41,1581.12 Q1_C.9@6688.41,1606.71 Q1_C.9@6688.41,1632.3 Q1_C.9@6707.2,1567.84 Q1_C.9@6707.2,1620 Q1_C.9@6721.77,1593.92 Q1_C.9@6742.83,1567.84 Q1_C.9@6742.83,1620 Q2_A.9@887.3,1345.53 Q2_A.9@887.3,1371.12 Q2_A.9@887.3,1396.71 Q2_A.9@887.3,1422.3 Q2_A.9@906.1,1357.84 Q2_A.9@906.1,1410 Q2_A.9@920.67,1383.92 Q2_A.9@941.73,1357.84 Q2_A.9@941.73,1410 Q2_B.9@3787.3,1345.53 Q2_B.9@3787.3,1371.12 Q2_B.9@3787.3,1396.71 Q2_B.9@3787.3,1422.3 Q2_B.9@3806.1,1357.84 Q2_B.9@3806.1,1410 Q2_B.9@3820.67,1383.92 Q2_B.9@3841.73,1357.84 Q2_B.9@3841.73,1410 Q2_C.9@6687.3,1345.53 Q2_C.9@6687.3,1371.12 Q2_C.9@6687.3,1396.71 Q2_C.9@6687.3,1422.3 Q2_C.9@6706.1,1357.84 Q2_C.9@6706.1,1410 Q2_C.9@6720.67,1383.92 Q2_C.9@6741.73,1357.84 Q2_C.9@6741.73,1410 Q3_A.9@1991.44,943.92 Q3_A.9@1991.44,996.08 Q3_A.9@2012.5,970 Q3_A.9@2027.07,943.92 Q3_A.9@2027.07,996.08 Q3_A.9@2045.87,931.61 Q3_A.9@2045.87,957.2 Q3_A.9@2045.87,982.8 Q3_A.9@2045.87,1008.39 Q3_B.9@4891.44,943.92 Q3_B.9@4891.44,996.08 Q3_B.9@4912.5,970 Q3_B.9@4927.07,943.92 Q3_B.9@4927.07,996.08 Q3_B.9@4945.87,931.61 Q3_B.9@4945.87,957.2 Q3_B.9@4945.87,982.8 Q3_B.9@4945.87,1008.39 Q3_C.9@7791.44,943.92 Q3_C.9@7791.44,996.08 Q3_C.9@7812.5,970 Q3_C.9@7827.07,943.92 Q3_C.9@7827.07,996.08 Q3_C.9@7845.87,931.61 Q3_C.9@7845.87,957.2 Q3_C.9@7845.87,982.8 Q3_C.9@7845.87,1008.39 Q4_A.9@1991.44,1148.92 Q4_A.9@1991.44,1201.08 Q4_A.9@2012.5,1175 Q4_A.9@2027.07,1148.92 Q4_A.9@2027.07,1201.08 Q4_A.9@2045.87,1136.61 Q4_A.9@2045.87,1162.2 Q4_A.9@2045.87,1187.8 Q4_A.9@2045.87,1213.39 Q4_B.9@4891.44,1148.92 Q4_B.9@4891.44,1201.08 Q4_B.9@4912.5,1175 Q4_B.9@4927.07,1148.92 Q4_B.9@4927.07,1201.08 Q4_B.9@4945.87,1136.61 Q4_B.9@4945.87,1162.2 Q4_B.9@4945.87,1187.8 Q4_B.9@4945.87,1213.39 Q4_C.9@7791.44,1148.92 Q4_C.9@7791.44,1201.08 Q4_C.9@7812.5,1175 Q4_C.9@7827.07,1148.92 Q4_C.9@7827.07,1201.08 Q4_C.9@7845.87,1136.61 Q4_C.9@7845.87,1162.2 Q4_C.9@7845.87,1187.8 Q4_C.9@7845.87,1213.39 Q5_A.9@889.13,1136.61 Q5_A.9@889.13,1162.2 Q5_A.9@889.13,1187.8 Q5_A.9@889.13,1213.39 Q5_A.9@907.93,1148.92 Q5_A.9@907.93,1201.08 Q5_A.9@922.5,1175 Q5_A.9@943.56,1148.92 Q5_A.9@943.56,1201.08 Q5_B.9@3789.13,1136.61 Q5_B.9@3789.13,1162.2 Q5_B.9@3789.13,1187.8 Q5_B.9@3789.13,1213.39 Q5_B.9@3807.93,1148.92 Q5_B.9@3807.93,1201.08 Q5_B.9@3822.5,1175 Q5_B.9@3843.56,1148.92 Q5_B.9@3843.56,1201.08 Q5_C.9@6689.13,1136.61 Q5_C.9@6689.13,1162.2 Q5_C.9@6689.13,1187.8 Q5_C.9@6689.13,1213.39 Q5_C.9@6707.93,1148.92 Q5_C.9@6707.93,1201.08 Q5_C.9@6722.5,1175 Q5_C.9@6743.56,1148.92 Q5_C.9@6743.56,1201.08 Q6_A.9@887.3,930.53 Q6_A.9@887.3,956.12 Q6_A.9@887.3,981.71 Q6_A.9@887.3,1007.3 Q6_A.9@906.1,942.84 Q6_A.9@906.1,995 Q6_A.9@920.67,968.92 Q6_A.9@941.73,942.84 Q6_A.9@941.73,995 Q6_B.9@3787.3,930.53 Q6_B.9@3787.3,956.12 Q6_B.9@3787.3,981.71 Q6_B.9@3787.3,1007.3 Q6_B.9@3806.1,942.84 Q6_B.9@3806.1,995 Q6_B.9@3820.67,968.92 Q6_B.9@3841.73,942.84 Q6_B.9@3841.73,995 Q6_C.9@6687.3,930.53 Q6_C.9@6687.3,956.12 Q6_C.9@6687.3,981.71 Q6_C.9@6687.3,1007.3 Q6_C.9@6706.1,942.84 Q6_C.9@6706.1,995 Q6_C.9@6720.67,968.92 Q6_C.9@6741.73,942.84 Q6_C.9@6741.73,995 Q7_A.9@1991.44,1358.92 Q7_A.9@1991.44,1411.08 Q7_A.9@2012.5,1385 Q7_A.9@2027.07,1358.92 Q7_A.9@2027.07,1411.08 Q7_A.9@2045.87,1346.61 Q7_A.9@2045.87,1372.2 Q7_A.9@2045.87,1397.8 Q7_A.9@2045.87,1423.39 Q7_B.9@4891.44,1358.92 Q7_B.9@4891.44,1411.08 Q7_B.9@4912.5,1385 Q7_B.9@4927.07,1358.92 Q7_B.9@4927.07,1411.08 Q7_B.9@4945.87,1346.61 Q7_B.9@4945.87,1372.2 Q7_B.9@4945.87,1397.8 Q7_B.9@4945.87,1423.39 Q7_C.9@7791.44,1358.92 Q7_C.9@7791.44,1411.08 Q7_C.9@7812.5,1385 Q7_C.9@7827.07,1358.92 Q7_C.9@7827.07,1411.08 Q7_C.9@7845.87,1346.61 Q7_C.9@7845.87,1372.2 Q7_C.9@7845.87,1397.8 Q7_C.9@7845.87,1423.39 Q8_A.9@1990.33,1574.4 Q8_A.9@1990.33,1626.56 Q8_A.9@2011.4,1600.48 Q8_A.9@2025.96,1574.4 Q8_A.9@2025.96,1626.56 Q8_A.9@2044.76,1562.1 Q8_A.9@2044.76,1587.69 Q8_A.9@2044.76,1613.28 Q8_A.9@2044.76,1638.87 Q8_B.9@4890.33,1574.4 Q8_B.9@4890.33,1626.56 Q8_B.9@4911.4,1600.48 Q8_B.9@4925.96,1574.4 Q8_B.9@4925.96,1626.56 Q8_B.9@4944.76,1562.1 Q8_B.9@4944.76,1587.69 Q8_B.9@4944.76,1613.28 Q8_B.9@4944.76,1638.87 Q8_C.9@7790.33,1574.4 Q8_C.9@7790.33,1626.56 Q8_C.9@7811.4,1600.48 Q8_C.9@7825.96,1574.4 Q8_C.9@7825.96,1626.56 Q8_C.9@7844.76,1562.1 Q8_C.9@7844.76,1587.69 Q8_C.9@7844.76,1613.28 Q8_C.9@7844.76,1638.87 SH-J1.0 SH-J2.0 U1.9@3115,2260 U2.6 U2.11 U3.3 U3.14 U4.1 U5_A.57@1390.28,1245.28 U5_A.57@1390.28,1298.43 U5_A.57@1390.28,1351.57 U5_A.57@1390.28,1404.72 U5_A.57@1443.43,1245.28 U5_A.57@1443.43,1298.43 U5_A.57@1443.43,1351.57 U5_A.57@1443.43,1404.72 U5_A.57@1496.57,1245.28 U5_A.57@1496.57,1298.43 U5_A.57@1496.57,1351.57 U5_A.57@1496.57,1404.72 U5_A.57@1549.72,1245.28 U5_A.57@1549.72,1298.43 U5_A.57@1549.72,1351.57 U5_A.57@1549.72,1404.72 U5_B.57@4290.28,1245.28 U5_B.57@4290.28,1298.43 U5_B.57@4290.28,1351.57 U5_B.57@4290.28,1404.72 U5_B.57@4343.43,1245.28 U5_B.57@4343.43,1298.43 U5_B.57@4343.43,1351.57 U5_B.57@4343.43,1404.72 U5_B.57@4396.57,1245.28 U5_B.57@4396.57,1298.43 U5_B.57@4396.57,1351.57 U5_B.57@4396.57,1404.72 U5_B.57@4449.72,1245.28 U5_B.57@4449.72,1298.43 U5_B.57@4449.72,1351.57 U5_B.57@4449.72,1404.72 U5_C.57@7190.28,1245.28 U5_C.57@7190.28,1298.43 U5_C.57@7190.28,1351.57 U5_C.57@7190.28,1404.72 U5_C.57@7243.43,1245.28 U5_C.57@7243.43,1298.43 U5_C.57@7243.43,1351.57 U5_C.57@7243.43,1404.72 U5_C.57@7296.57,1245.28 U5_C.57@7296.57,1298.43 U5_C.57@7296.57,1351.57 U5_C.57@7296.57,1404.72 U5_C.57@7349.72,1245.28 U5_C.57@7349.72,1298.43 U5_C.57@7349.72,1351.57 U5_C.57@7349.72,1404.72

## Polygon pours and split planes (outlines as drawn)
GND_ISO on Signal Layer 1 "SIGNAL_LAYER_1_GND_ISO_P028" (solid, remove dead copper, pour order 28): 6865,2650 6865,2265 8300,2265 8300,2050.98 8700,2050.98 8700,2650
GND on Signal Layer 1 "SIGNAL_LAYER_1_GND_P022" (solid, remove dead copper, pour order 22): 6735,2650 50,2650 50,550 8700,550 8700,1950 8200,1950 8200,2130 6735,2130
3.3V_ISO on Signal Layer 2 "SIGNAL_LAYER_2_3.3V_ISO_P020" (solid, remove dead copper, pour order 20): 6865,2650 8700,2650 8700,2050 8300,2050 8300,2265 6865,2265
VPWR on Signal Layer 2 "SIGNAL_LAYER_2_VPWR_P019" (solid, remove dead copper, pour order 19): 50,2650 6735,2650 6735,2130 8200,2130 8200,1950 8700,1950 8700,550 50,550
GND on Bottom Layer "BOTTOM_LAYER_GND_P024" (solid, remove dead copper, pour order 24): 50,2650 6735,2650 6735,2130 8200,2130 8200,1950 8700,1950 8700,550 50,550
GND_ISO on Bottom Layer "BOTTOM_LAYER_GND_ISO_P025" (solid, remove dead copper, pour order 25): 6865,2650 6865,2265 8300,2265 8300,2050 8700,2050 8700,2650
GND_ISO on Top Layer "TOP_LAYER_GND_ISO_P026" (solid, remove dead copper, pour order 26): 6865,2650 6865,2265 8300,2265 8300,2050 8700,2050 8700,2650
GND on Top Layer "TOP_LAYER_GND_P023" (solid, remove dead copper, pour order 23): 50,2650 6735,2650 6735,2130 8200,2130 8200,1950 8700,1950 8700,550 50,550
PSE_3.3V on Top Layer "TOP_LAYER_PSE_3.3V_P021" (solid, remove dead copper, pour order 21): 3285,2650 3285,2495 3575,2495 3575,2650
NetC1_1 on Top Layer "TOP_LAYER_NETC1_1_P018" (solid, remove dead copper, pour order 18): 3285,2330 3575,2330 3575,2455 3285,2455

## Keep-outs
Keep-Out Layer:
  text ".Layer_Name" at 577,-858.49 h60

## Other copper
Top Layer:
  text ".Layer_Name" at 602,-863.49 h60
Signal Layer 1:
  text ".Layer_Name" at 577,-858.49 h60
Signal Layer 2:
  text ".Layer_Name" at 602,-858.49 h60
Bottom Layer:
  text ".Layer_Name" at 577,-858.49 h60

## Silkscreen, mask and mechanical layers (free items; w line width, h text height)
Top Overlay:
  text "'.PRJ_Number'.PCB_Rev" at 165,2490 h130
  text "PSE_A3" at 5065,2130 h72.83 r90
  text "PSE_A4" at 5170.17,2130 h72.83 r90
  text ".Layer_Name" at 577,-858.49 h60
Bottom Overlay:
  text ".Layer_Name" at 577,-858.49 h60
Top Paste:
  text ".Layer_Name" at 577,-858.49 h60
Bottom Paste:
  text ".Layer_Name" at 577,-858.49 h60
Top Solder:
  text ".Layer_Name" at 577,-858.49 h60
  text ".Layer_Name" at 577,-858.49 h60
Bottom Solder:
  text ".Layer_Name" at 577,-858.49 h60
Drill Guide:
  text ".Layer_Name" at 577,-858.49 h60
M1 Board Outline:
  the board outline again, w10
  text ".Layer_Name" at 577,-858.49 h60
M2 Board Dimensions:
  rectangle: 0,-275 125,-150
  rectangle: 125,-400 500,-275
  lines w7: 0,-275 1000,-275 ; 125,-400 125,-150 ; 250,-400 250,-150 ; 500,-400 500,-150 ; 750,-400 750,-150 ; 0,-400 1000,-400 1000,-150 0,-150 0,-400
  text ".Layer_Name" at 577,-858.49 h60
M3 3D STEP Top:
  text ".Layer_Name" at 577,-858.49 h60
M4 3D STEP Bottom:
  text ".Layer_Name" at 577,-858.49 h60
M5 Assembly Top:
  lines w10: -292,-930.17 6308,-930.17 ; -292,-726.83 6310,-726.83 ; -292,-523.5 -292,-1133.5 3713,-1133.5 6310,-1133.5 6310,-523.5 -291.5,-523.5 -291.5,-1133.5 1284,-1133.5 ; 2173,-1133.5 2173,-523.5 ; 3440,-726.83 3440,-523.5 ; 4280,-726.83 4280,-523.5 ; 4902,-1140 4902,-937.17
  text "COMPONENTS MARKED 'DNP' SHOULD NOT BE POPULATED." at 1153.5,-318.5 h60
  text "ASSEMBLY VARIANT:" at 1153,-434 h60
  text ".VariantName" at 2189,-434 h60
  text "PCB VIEWED FROM TOP SIDE" at -228.5,-655.67 h60
  text "BOARD #:" at 2248,-655.67 h60
  text ".PRJ_Number" at 2793.5,-655.67 h60
  text "REV:" at 3638,-655.67 h60
  text ".PCB_Rev" at 3929.5,-655.67 h60
  text "SVN REV:" at 4476,-655.67 h60
  text ".VersionControl_RevNumber" at 4982,-655.67 h60
  text "TID #:" at 2248,-859 h60
  text ".TID" at 2793.5,-859 h60
  text "PLOT NAME =" at -228.5,-1064.34 h60
  text ".plot_File_Name" at 577,-1064.34 h60
  text "GENERATED    :" at 2250,-1064.34 h60
  text ".Print_Date" at 3119.5,-1064.34 h60
  text ".Print_Time" at 3848.5,-1064.34 h60
  text "TEXAS INSTRUMENTS" at 5113,-1064.34 h60
M6 Assembly Bottom:
  lines w10: -292.5,-727.33 6309.5,-727.33 ; -290.5,-930.67 6309.5,-930.67 ; 1115.5,-1140.5 1115.5,-937.67 ; 1737.5,-727.33 1737.5,-524 ; 2577.5,-727.33 2577.5,-524 ; 3844.5,-1134 3844.5,-524 ; 4733.5,-1134 6309,-1134 6309,-524 -292.5,-524 -292.5,-1134 2304.5,-1134 6309.5,-1134 6309.5,-524
  text "COMPONENTS MARKED 'DNP' SHOULD NOT BE POPULATED." at 6102,-318 h60
  text ".VariantName" at 5058,-434 h60
  text "ASSEMBLY VARIANT:" at 6097,-434 h60
  text ".VersionControl_RevNumber" at 1035.5,-656.17 h60
  text "SVN REV:" at 1541.5,-656.17 h60
  text ".PCB_Rev" at 2088,-656.17 h60
  text "REV:" at 2379.5,-656.17 h60
  text ".PRJ_Number" at 3224,-656.17 h60
  text "BOARD #:" at 3769.5,-656.17 h60
  text "PCB VIEWED FROM BOTTOM SIDE" at 6246,-656.17 h60
  text ".TID" at 3224,-859.5 h60
  text "TID #:" at 3769.5,-859.5 h60
  text "TEXAS INSTRUMENTS" at 904.5,-1064.84 h60
  text ".Print_Time" at 2169,-1064.84 h60
  text ".Print_Date" at 2898,-1064.84 h60
  text "GENERATED    :" at 3767.5,-1064.84 h60
  text ".plot_File_Name" at 5440.5,-1064.84 h60
  text "PLOT NAME =" at 6246,-1064.84 h60
M9 Title Sheet:
  drawing of 57 lines, arcs and shapes, not listed
  text "1" at 739.84,8036.5 h70
  text "2" at 3235.5,8036.5 h70
  text "3" at 5724.84,8036.5 h70
  text "4" at 8231.51,8036.5 h70
  text "5" at 10730.5,8036.5 h70
  text "6" at 13235.5,8036.5 h70
  text "A" at -416.5,6893.5 h70
  text "A" at 14383.5,6893.5 h70
  text "B" at -416.5,4513.5 h70
  text "B" at 14383.5,4513.5 h70
  text "C" at -416.5,2138.5 h70
  text "C" at 14383.5,2138.5 h70
  text "PROJECT TITLE:" at 11343.5,277.5 h45
  text ".PRJ_Title" at 11393.5,144.17 h70
  text "DESIGNED FOR:" at 11343.5,-23.5 h45
  text ".PRJ_Customer" at 11393.5,-163.5 h70
  text "D" at -416.5,-231.5 h70
  text "D" at 14383.5,-231.5 h70
  text "FILE NAME:" at 11343.5,-323.5 h45
  text ".PCB_File_Name_No_Path" at 11393.5,-443.5 h70
  text "Texas Instruments (TI) and/or its licensors do not warrant the accuracy or completeness of this specification" at 6374,-605.34 h45
  text "ENGINEER:" at 11343.5,-613.5 h45
  text "LAYOUT BY:" at 12848.5,-613.5 h45
  text "or any information contained therein. TI and/or its licensors do not warrant that this design will meet" at 6329.01,-718 h45
  text ".PRJ_Engineer" at 11393.5,-768.49 h70
  text ".PCB_Layout" at 12899,-768.49 h70
  text "the specifications, will be suitable for your application or fit for any particular purpose, or will operate in" at 6329.01,-830.67 h45
  text ".Layer_Name" at 577,-858.49 h60
  text "ALTIUM DESIGNER VERSION:" at 12848.5,-923.5 h45
  text "an implementation. TI and/or its licensors do not warrant that the design is production worthy. You should" at 6329.01,-943.33 h45
  text "completely validate and test your design implementation to confirm the system functionality for your application." at 6374,-1056 h45
  text ".print_Scale" at 11393.5,-1056.83 h70
  text ".Application_BuildNumber" at 12899,-1056.83 h70
  text "1" at 739.84,-1263.5 h70
  text "2" at 3235.5,-1263.5 h70
  text "3" at 5724.84,-1263.5 h70
  text "4" at 8231.51,-1263.5 h70
  text "5" at 10730.5,-1263.5 h70
  text "6" at 13235.5,-1263.5 h70
M10 Fab Notes:
  drawing of 189 lines, arcs and shapes, not listed
  text "DESIGN INFORMATION" at 12382.02,6356.17 h60
  text "MIN. TRACK WIDTH:" at 11737.46,6224.05 h60
  text "8" at 12833.7,6224.05 h60
  text "MIL" at 12988.46,6224.05 h60
  text "MIN. CLEARANCE:" at 11737.46,6099.92 h60
  text "0.2" at 12773.7,6099.93 h60
  text "mm" at 12988.46,6099.92 h60
  text "MIN. VIA PAD SIZE:" at 11737.46,5975.8 h60
  text "24" at 12803.71,5975.8 h60
  text "MIL" at 12988.46,5975.8 h60
  text "0.05mm (2MIL)" at 12432.46,5845.9 h60
  text "MINIMUM ANNULAR RING" at 11408.23,5837.67 h60
  text "EXTERNAL" at 13140.46,5837.67 h60
  text "PER" at 11608.23,5727.55 h60
  text "IPC-D-275 CLASS 2 LEVEL C" at 11828.23,5727.54 h60
  text "MIL, HOLES" at 13316.46,5627.07 h60
  text "+/-" at 12924,5618.48 h60
  text "+/-" at 13778,5618.48 h60
  text "REGISTRATION TOLERANCES:" at 11408.23,5617.42 h60
  text "METAL" at 12608,5617.42 h60
  text "5" at 13184.2,5617.42 h60
  text "3" at 14017.2,5617.42 h60
  text "MIL" at 14133.46,5617.42 h60
  text "HOLE SIZE TOLERANCE (UNLESS OTHERWISE SPECIFIED):" at 11408.23,5519.1 h60
  text "+/-" at 13778,5516.23 h60
  text "3" at 14017.2,5515.17 h60
  text "MIL" at 14133.46,5515.17 h60
  text "MATERIAL:" at 11333.46,5377.52 h60
  text "FR-4 High Tg" at 12319.9,5249 h60
  text "X" at 12175.46,5241.01 h60
  text "FR-408" at 11754.46,5236.49 h60
  text "OTHER" at 13242.46,5236.49 h60
  text "62 MIL (1.6mm) +/-10%" at 12074.56,5093.46 h60
  text "X" at 11954.46,5091.01 h60
  text "THICKNESS:" at 11408.23,5085.24 h60
  text "OTHER" at 13359.46,5085.24 h60
  text "TOLERANCE:" at 11408.23,4946.92 h60
  text "X" at 12256.46,4946.92 h60
  text "ANSI IPC-6012 TYPE 3 CLASS 2" at 12434.48,4946.92 h60
  text "OTHER +/-" at 12434.46,4802.73 h60
  text "BOW & TWIST:" at 11408.23,4657.54 h60
  text "X" at 12256.46,4657.54 h60
  text "ANSI IPC-6012 TYPE 3 CLASS 2" at 12434.48,4657.54 h60
  text "OTHER +/-" at 12434.46,4510.85 h60
  text "DRILLING:" at 11333.46,4380.23 h60
  text "NC_DRILL FILES" at 13094.46,4275.04 h60
  text "REFERENCE:" at 11408.23,4271.1 h60
  text "X" at 12065.46,4271.01 h60
  text "AS SHOWN" at 12243.46,4271.1 h60
  text "X" at 12966.46,4271.1 h60
  text "OTHER" at 13392.46,4128.85 h60
  text "PTH COPPER THICKNESS:" at 11407.91,4125.32 h60
  text "X" at 12547.14,4125.32 h60
  text "20-30 um" at 12675.14,4125.32 h60
  text "BOARD FINISH:" at 11333.46,3977.73 h60
  text "SILKSCREEN:" at 11488.68,3867.6 h60
  text "X" at 12446.46,3867.6 h60
  text "TOP" at 12563.46,3867.6 h60
  text "X" at 12956.46,3867.6 h60
  text "BOTTOM" at 13074.46,3867.6 h60
  text "SILKSCREEN COLOR:" at 11488.68,3712.41 h60
  text "X" at 12445.46,3712.41 h60
  text "WHITE" at 12563.46,3712.41 h60
  text "OTHER" at 13074.46,3712.41 h60
  text "X" at 12576.46,3568.96 h60
  text "GREEN" at 12694.46,3568.96 h60
  text "OTHER" at 13312.46,3568.96 h60
  text "SOLDER RESIST COLOR:" at 11488.68,3562.1 h60
  text "X" at 12576.46,3414.71 h60
  text "MATTE" at 12694.46,3414.71 h60
  text "SEMI-GLOSS" at 13312,3414.07 h60
  text "IMMERSION GOLD (ENIG)" at 12394.46,3241.94 h60
  text "ENEPIG" at 13732,3234.72 h60
  text "SURFACE FINISH:" at 11333.46,3233.72 h60
  text "X" at 12216.46,3233.72 h60
  text "IMM. TIN/SILVER OR EQUIV" at 11663,3096.4 h60
  text "OTHER" at 13094.46,3092.47 h60
  text "ARRAY/PANEL:" at 11333.46,2937.09 h60
  text "CUT AND TRIM PER M1 BOARD OUTLINE" at 12394.46,2928.87 h60
  text "N.C. ROUTE" at 12394.46,2792.9 h60
  text "X" at 13082.46,2792.9 h60
  text "V. SCORE" at 13260.46,2792.9 h60
  text "CERTIFICATION:" at 11333.46,2663.77 h60
  text "MATERIALS AND WORKMANSHIP FOR ALL PCBS" at 12058.46,2663.77 h60
  text "TO MEET OR EXCEED THE REQUIREMENTS OF:" at 12058.46,2569.71 h60
  text "X" at 11695.97,2441.08 h60
  text "ANSI IPC-A-600F CLASS ->" at 11823.96,2441.08 h60
  text "X" at 13471.97,2441.08 h60
  text "2" at 13581.96,2441.08 h60
  text "1" at 13266.96,2439.58 h60
  text "3" at 13935.96,2439.58 h60
  text "X" at 12507.97,2293.39 h60
  text "RoHS" at 12635.96,2293.39 h60
  text "OTHER" at 13280.36,2293.39 h60
  text "PER ORDER" at 13677.42,2293.39 h60
  text "ALL BOARDS MUST MEET OR EXCEED UL94-V0 REQUIREMENTS." at 11361,2139.57 h60
  text "PCB MUST BEAR THE UL94V-0 UL REGISTERED MATERIAL ID NUMBER" at 11361,2023.5 h60
  text "ADDITIONAL REQUIREMENTS:" at 11333.46,1854.08 h60
  text "MICROSECTION:" at 11408.23,1746.95 h60
  text "YES" at 12313.96,1746.95 h60
  text "REQUIRED" at 13175.46,1602.62 h60
  text "BARE BOARD ELEC. TEST:" at 11408.23,1599.76 h60
  text "NONE" at 12713.96,1599.76 h60
  text "X" at 13057.46,1599.76 h60
  text "PER ORDER" at 13767.46,1599.76 h60
  text "XX MIL VIAS REQUIRE NON-CONDUCTIVE FILL AND PLANARIZE" at 11576.38,1394.82 h59
  text "XX MIL VIAS REQUIRE CONDUCTIVE FILL AND PLANARIZE" at 11584.38,1290.84 h60
  text "OUTER XX MIL TRACES REQUIRE 50 OHM SINGLE-ENDED IMPEDANCE" at 11583.39,1127.46 h58
  text "LAYER 2 & 3 (INNER LAYERS) XX MIL WIDE, XX MIL SPACE / TRACES REQUIRE 100 OHM DIFFERENTIAL IMPEDANCE" at 11575.39,891.74 h60
  text ".Layer_Name" at 577,-858.49 h60
M11 Gerber Information:
  lines w10: -292,-930.17 6308,-930.17 ; -292,-726.83 6310,-726.83 ; -292,-523.5 -292,-1133.5 3713,-1133.5 6310,-1133.5 6310,-523.5 -291.5,-523.5 -291.5,-1133.5 1284,-1133.5 ; 2173,-1133.5 2173,-523.5 ; 3440,-726.83 3440,-523.5 ; 4280,-726.83 4280,-523.5 ; 4902,-1140 4902,-937.17
  text "ALL ARTWORK VIEWED FROM TOP SIDE" at -228.5,-655.67 h60
  text "BOARD #:" at 2248,-655.67 h60
  text ".PRJ_Number" at 2793.5,-655.67 h60
  text "REV:" at 3638,-655.67 h60
  text ".PCB_Rev" at 3929.5,-655.67 h60
  text "SVN REV:" at 4476,-655.67 h60
  text ".VersionControl_RevNumber" at 4982,-655.67 h60
  text "LAYER NAME =" at -228.5,-858.49 h60
  text "TID #:" at 2248,-859 h60
  text ".TID" at 2793.5,-859 h60
  text "PLOT NAME =" at -228.5,-1064.34 h60
  text ".plot_File_Name" at 577,-1064.34 h60
  text "GENERATED    :" at 2250,-1064.34 h60
  text ".Print_Date" at 3119.5,-1064.34 h60
  text ".Print_Time" at 3848.5,-1064.34 h60
  text "TEXAS INSTRUMENTS" at 5113,-1064.34 h60
M12 Stackup:
  drawing of 295 lines, arcs and shapes, not listed
  text "Layer" at 9756.2,7840 h60
  text "Name" at 10166.11,7840 h60
  text "Material" at 11105.85,7840 h60
  text "Thickness" at 11965.62,7840 h60
  text "Constant" at 12615.46,7840 h60
  text "Board Layer Stack" at 13185.32,7840 h60
  text "1" at 9756.2,7720 h60
  text "Top Overlay" at 10166.11,7720 h60
  text "2" at 9756.2,7600 h60
  text "Top Solder" at 10166.11,7600 h60
  text "Solder Resist" at 11105.85,7600 h60
  text "0.40mil" at 11965.62,7600 h60
  text "3.5" at 12615.46,7600 h60
  text "3" at 9756.2,7480 h60
  text "Top Layer" at 10166.11,7480 h60
  text "Copper" at 11105.85,7480 h60
  text "2.80mil" at 11965.62,7480 h60
  text "4" at 9756.2,7360 h60
  text "Dielectric1" at 10166.11,7360 h60
  text "FR-4 High TG" at 11105.85,7360 h60
  text "10.00mil" at 11965.62,7360 h60
  text "4.2" at 12615.46,7360 h60
  text "5" at 9756.2,7240 h60
  text "Signal Layer 1" at 10166.11,7240 h60
  text "Copper" at 11105.85,7240 h60
  text "2.80mil" at 11965.62,7240 h60
  text "6" at 9756.2,7120 h60
  text "Dielectric 2" at 10166.11,7120 h60
  text "FR-4 High TG" at 11105.85,7120 h60
  text "30.00mil" at 11965.62,7120 h60
  text "4.2" at 12615.46,7120 h60
  text "7" at 9756.2,7000 h60
  text "Signal Layer 2" at 10166.11,7000 h60
  text "Copper" at 11105.85,7000 h60
  text "2.80mil" at 11965.62,7000 h60
  text "8" at 9756.2,6880 h60
  text "Dielectric 3" at 10166.11,6880 h60
  text "FR-4 High TG" at 11105.85,6880 h60
  text "10.00mil" at 11965.62,6880 h60
  text "4.2" at 12615.46,6880 h60
  text "9" at 9756.2,6760 h60
  text "Bottom Layer" at 10166.11,6760 h60
  text "Copper" at 11105.85,6760 h60
  text "2.80mil" at 11965.62,6760 h60
  text "10" at 9756.2,6640 h60
  text "Bottom Solder" at 10166.11,6640 h60
  text "Solder Resist" at 11105.85,6640 h60
  text "0.40mil" at 11965.62,6640 h60
  text "3.5" at 12615.46,6640 h60
  text "11" at 9756.2,6520 h60
  text "Bottom Overlay" at 10166.11,6520 h60
  text ".Layer_Name" at 577,-858.49 h60
M13 Component Bodies Top:
  text ".Layer_Name" at 577,-858.49 h60
M14 Component Bodies Bottom:
  text ".Layer_Name" at 577,-858.49 h60
M15 Courtyards Top:
  text ".Layer_Name" at 577,-858.49 h60
M16 Courtyards Bottom:
  text ".Layer_Name" at 577,-858.49 h60
Drill Drawing:
  circle w10: c5558.72,3389.64 r27.63
  lines w10: 5531.09,3237.7 5586.34,3237.7 5586.34,3292.95 5531.09,3292.95 5531.09,3237.7 ; 5531.09,3500.15 5544.9,3500.15 5558.72,3486.34 5572.53,3500.15 5586.34,3500.15 5572.53,3513.96 5586.34,3527.78 5572.53,3527.78 5558.72,3541.59 5544.9,3527.78 5531.09,3527.78 5544.9,3513.96 5531.09,3500.15 ; 5531.09,3665.91 5586.34,3665.91 5558.72,3610.66 5531.09,3665.91
  lines w12: 5481,3200.4 8712.49,3200.4 ; 5481,3697.68 8712.49,3697.68 ; 5818.86,3076.08 5818.86,3822 ; 6150.86,3076.08 6150.86,3822 ; 6787.43,3076.08 6787.43,3822 ; 7046.57,3076.08 7046.57,3822 ; 7421.72,3076.08 7421.72,3822 ; 8146.05,3076.08 8146.05,3822 ; 5481,3076.08 8712.49,3076.08 8712.49,3822 5481,3822 5481,3076.08
  text "Symbol" at 5555.59,3734.98 h72
  text "Quantity" at 5856.16,3734.98 h72
  text "Finished Hole Size" at 6188.16,3734.98 h72
  text "Plated" at 6824.72,3734.98 h72
  text "Hole Type" at 7083.86,3734.98 h72
  text "Drill Layer Pair" at 7459.02,3734.98 h72
  text "Hole Tolerance" at 8183.35,3734.98 h72
  text "71" at 5856.16,3610.66 h60
  text "7.87mil (0.200mm)" at 6188.16,3610.66 h60
  text "PTH" at 6824.72,3610.66 h60
  text "Round" at 7083.86,3610.66 h60
  text "Top Layer - Bottom Layer" at 7459.02,3610.66 h60
  text "282" at 5856.16,3486.34 h60
  text "12.00mil (0.305mm)" at 6188.16,3486.34 h60
  text "PTH" at 6824.72,3486.34 h60
  text "Round" at 7083.86,3486.34 h60
  text "Top Layer - Bottom Layer" at 7459.02,3486.34 h60
  text "1" at 5856.16,3362.02 h60
  text "16.00mil (0.406mm)" at 6188.16,3362.02 h60
  text "PTH" at 6824.72,3362.02 h60
  text "Round" at 7083.86,3362.02 h60
  text "Top Layer - Bottom Layer" at 7459.02,3362.02 h60
  text "153" at 5856.16,3237.7 h60
  text "40.00mil (1.016mm)" at 6188.16,3237.7 h60
  text "PTH" at 6824.72,3237.7 h60
  text "Round" at 7083.86,3237.7 h60
  text "Top Layer - Bottom Layer" at 7459.02,3237.7 h60
  text "507 Total" at 5856.16,3113.38 h60
  text ".Layer_Name" at 577,-858.49 h60
M17 Embedded Cavity:
  text ".Layer_Name" at 577,-858.49 h60
M18 Embedded Assembly:
  text ".Layer_Name" at 577,-858.49 h60
M19 Embedded Keepout:
  text ".Layer_Name" at 577,-858.49 h60

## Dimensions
0,-400 to 1000,-400 on M2 Board Dimensions
0,0 to 0,2700 on M2 Board Dimensions
0,0 to 8750,0 on M2 Board Dimensions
